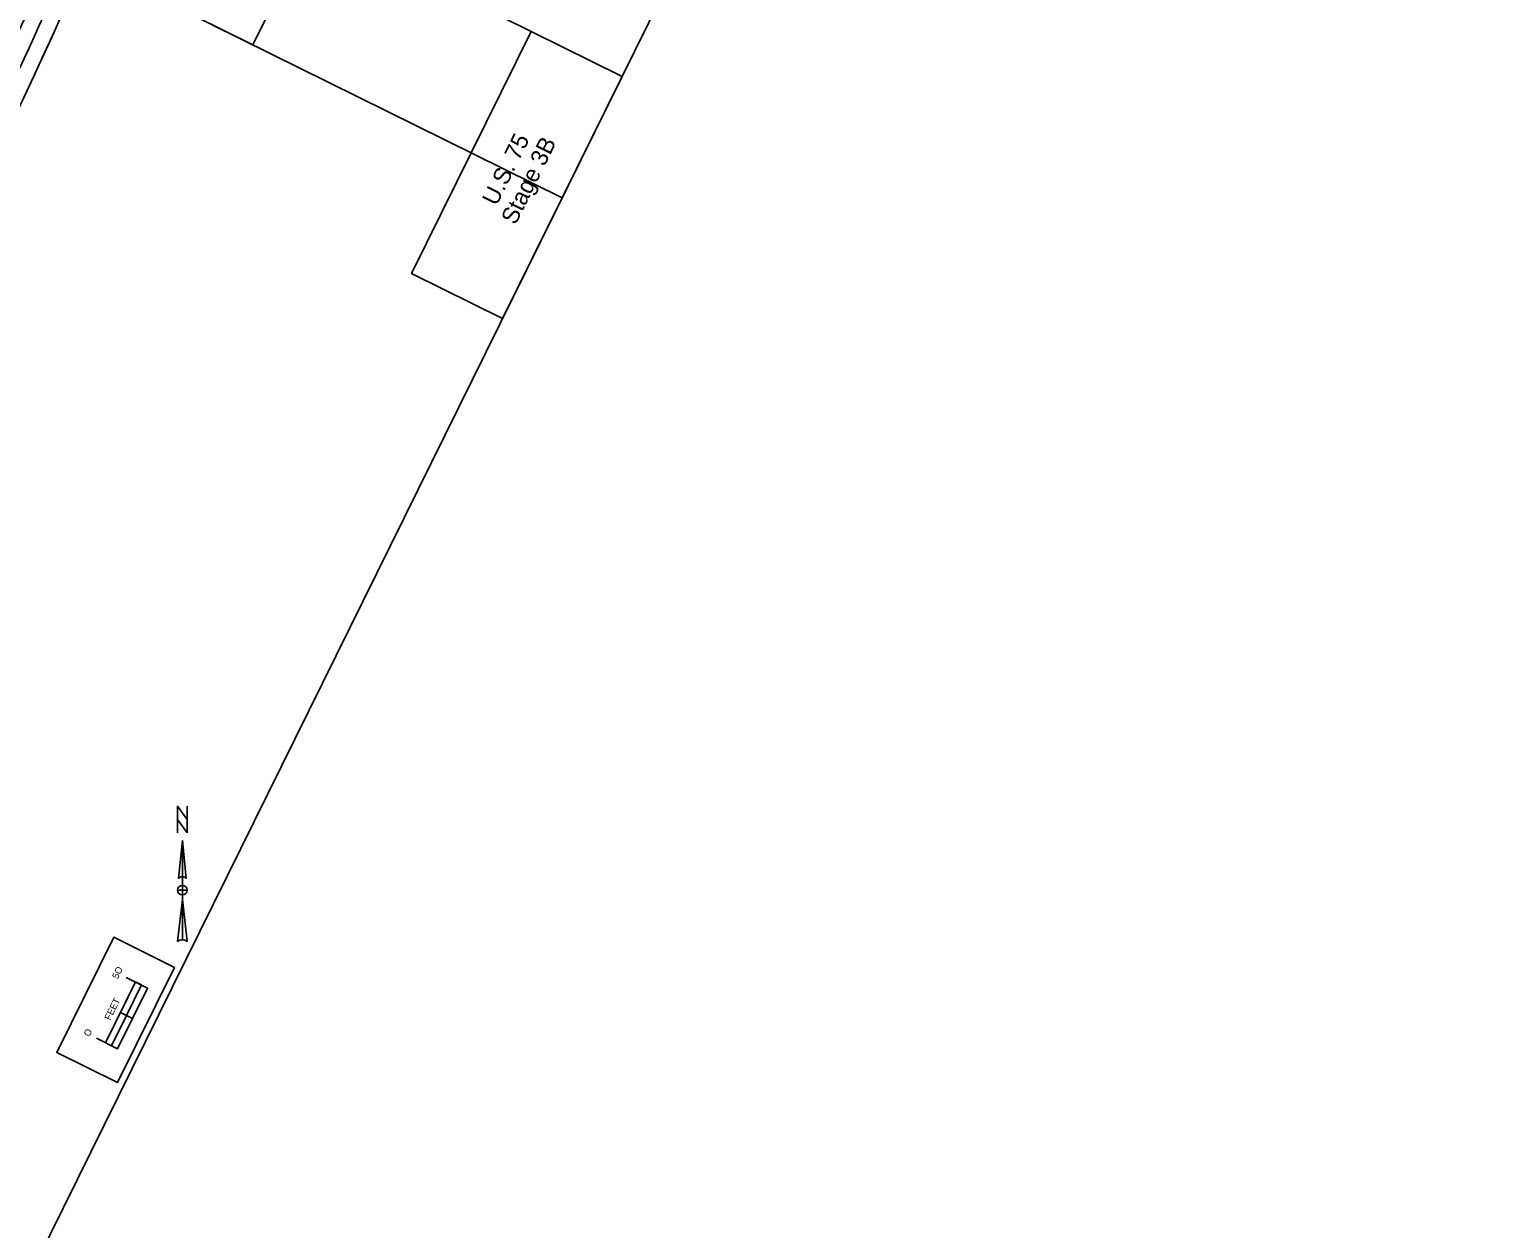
# Model space of a CAD drawing. Extents: x 14104283 to 14120882, y 8635219 to 8671666.
# Drawn here: x 14119794 to 14120882, y 8669052 to 8669937 of the extents above; entities that cross this region are included whole.
import ezdxf

# ---------------------------------------------------------------- set-up
doc = ezdxf.new("R2010")
doc.units = 0
for name, color, linetype in [('dsnCellsNorthArrow', 7, 'Continuous'), ('dsnCellsScaleBlock', 7, 'Continuous'), ('dsnNonPlotable', 7, 'Continuous'), ('dsnPaintExistingBrokenLaneLineWhite', 7, 'Continuous'), ('dsnPaintExistingEdgeLineRightWhite', 7, 'Continuous'), ('dsnPaintExistingNoPassingYellow', 7, 'Continuous'), ('dsnShadingPaved', 7, 'Continuous'), ('dsnTextOverlapOdd', 7, 'Continuous')]:
    doc.layers.add(name, color=color, linetype=linetype)

msp = doc.modelspace()

# ---------------------------------------------------------------- linework, layer by layer
at = {"layer": 'dsnCellsNorthArrow'}
for p, q in [((14119906.8, 8669338.4), (14119909.6, 8669310.3)), ((14119906.8, 8669338.4), (14119906.8, 8669265.2)), ((14119904, 8669310.3), (14119904, 8669310.3)), ((14119904.1, 8669310.5), (14119904.6, 8669311.1)), ((14119906.8, 8669298.3), (14119906.8, 8669298.3)), ((14119903.3, 8669263.8), (14119906.8, 8669294.8))]:
    msp.add_line(p, q, dxfattribs=at)
msp.add_lwpolyline([(14119910.3, 8669344.1), (14119903.3, 8669353.9), (14119903.3, 8669363.8), (14119910.3, 8669353.9)], close=True, dxfattribs=at)
for points in [[(14119903.3, 8669344.1), (14119903.3, 8669363.8), (14119910.3, 8669353.9), (14119910.3, 8669363.8)], [(14119904, 8669310.3), (14119906.8, 8669338.4), (14119906.8, 8669311.7)], [(14119906.8, 8669298.3), (14119906.8, 8669301.8), (14119903.3, 8669301.8)], [(14119910.3, 8669301.8), (14119906.8, 8669301.8), (14119906.8, 8669305.3)], [(14119906.8, 8669265.2), (14119906.8, 8669294.8), (14119910.3, 8669263.8)]]:
    msp.add_lwpolyline(points, dxfattribs=at)
for centre, radius, start, end in [((14119906.8, 8669308.2), 3.52, 90.0204, 143.1257), ((14119906.8, 8669308.2), 3.52, 36.8481, 90.0218), ((14119906.8, 8669301.8), 3.52, 90, 180), ((14119906.8, 8669301.8), 3.52, 180, 270), ((14119906.8, 8669301.8), 3.52, 0, 90), ((14119906.8, 8669301.8), 3.52, 270, 360), ((14119906.8, 8669260.1), 5.1, 89.9894, 133.619), ((14119906.8, 8669260.1), 5.11, 46.4021, 90.0006)]:
    msp.add_arc(centre, radius, start, end, dxfattribs=at)
at = {"layer": 'dsnCellsScaleBlock'}
msp.add_line((14119870, 8669207.1), (14119861.1, 8669211.5), dxfattribs=at)
msp.add_line((14119870, 8669207.1), (14119861.1, 8669211.5), dxfattribs=at)
for points in [[(14119814, 8669181.8), (14119856.1, 8669267), (14119901, 8669244.8), (14119858.8, 8669159.7)], [(14119858.8, 8669159.7), (14119814, 8669181.8), (14119856.1, 8669267), (14119901, 8669244.8)], [(14119865.5, 8669209.3), (14119876.6, 8669231.8), (14119872.2, 8669234), (14119861.1, 8669211.5)], [(14119859, 8669184.7), (14119870, 8669207.1), (14119865.5, 8669209.3), (14119854.4, 8669186.9)]]:
    msp.add_lwpolyline(points, close=True, dxfattribs=at)
for points in [[(14119843.3, 8669192.5), (14119859, 8669184.7), (14119881.1, 8669229.5), (14119865.4, 8669237.3)], [(14119850, 8669189.1), (14119872.2, 8669234)]]:
    msp.add_lwpolyline(points, dxfattribs=at)
at = {"layer": 'dsnNonPlotable'}
for points in [[(14119282, 8670260.6), (14119976.8, 8671665.7), (14120882.2, 8671218.1), (14120187.4, 8669813)], [(14119506.2, 8670149.8), (14120200.9, 8671554.9), (14120653.6, 8671331.1), (14119958.8, 8669926)], [(14118631.6, 8668945.1), (14119326.4, 8670350.2), (14120231.7, 8669902.6), (14119537, 8668497.5)]]:
    msp.add_lwpolyline(points, close=True, dxfattribs=at)
at = {"layer": 'dsnPaintExistingBrokenLaneLineWhite'}
for centre, radius, start, end in [((14115417.9, 8671831.2), 4741.3, 336.0305, 339.3915), ((14115455.3, 8671919.9), 4775.4, 334.8735, 338.2325)]:
    msp.add_arc(centre, radius, start, end, dxfattribs=at)
at = {"layer": 'dsnPaintExistingEdgeLineRightWhite'}
msp.add_arc((14115455.3, 8671919.9), 4787.4, 334.8735, 338.2325, dxfattribs=at)
at = {"layer": 'dsnPaintExistingNoPassingYellow'}
for centre, radius, start, end in [((14115417.9, 8671831.2), 4753.3, 336.0305, 339.3915), ((14115455.3, 8671919.9), 4763.4, 334.8735, 338.2325)]:
    msp.add_arc(centre, radius, start, end, dxfattribs=at)
at = {"layer": 'dsnShadingPaved'}
msp.add_open_spline([(14119812.9, 8669937.4), (14119812.6, 8669936.7), (14119812.3, 8669936.1), (14119811.7, 8669934.7), (14119811.4, 8669934.1), (14119810.5, 8669932.1), (14119809.9, 8669930.8), (14119808.1, 8669926.8), (14119806.9, 8669924.2), (14119803.2, 8669916.3), (14119798.4, 8669905.7), (14119792.3, 8669892.6), (14119788.6, 8669884.7), (14119786.7, 8669880.8), (14119786.1, 8669879.5), (14119785.2, 8669877.5), (14119784.9, 8669876.9), (14119784.5, 8669876.1), (14119784.5, 8669876), (14119784.4, 8669875.9), (14119784.4, 8669875.9), (14119784.4, 8669875.9), (14119784.4, 8669875.9), (14119784.4, 8669875.9), (14119784.4, 8669875.9), (14119784.4, 8669875.9), (14119784.3, 8669875.8), (14119784.3, 8669875.8), (14119784.2, 8669875.5), (14119784.2, 8669875.4), (14119784.1, 8669875.2), (14119784, 8669875.1), (14119784, 8669875.1), (14119783.9, 8669874.9), (14119783.8, 8669874.6), (14119783.7, 8669874.4), (14119783.6, 8669874.2)], degree=3, dxfattribs=at)
at = {"layer": 'dsnTextOverlapOdd'}
for points in [[(14120231.7, 8669902.6), (14120143.4, 8669724), (14120076.2, 8669757.2), (14120164.5, 8669935.8)], [(14120076.2, 8669757.2), (14120164.5, 8669935.8), (14120231.7, 8669902.6), (14120143.4, 8669724)]]:
    msp.add_lwpolyline(points, close=True, dxfattribs=at)

# ---------------------------------------------------------------- texts
at = {"layer": 'dsnCellsScaleBlock'}
for s, p in [('5O', (14119859.1, 8669235.8)), ('FEET', (14119853.5, 8669205.3)), ('O', (14119838.1, 8669193.2))]:
    msp.add_text(s, height=5, rotation=63.6912, dxfattribs=at).set_placement(p)
at = {"layer": 'dsnTextOverlapOdd'}
for s, p in [('U.S. 75', (14120138.9, 8669806.5)), ('Stage 3B', (14120152.9, 8669792.4))]:
    msp.add_text(s, height=12.5, rotation=63.6912, dxfattribs=at).set_placement(p)

doc.saveas('drawing.dxf')
